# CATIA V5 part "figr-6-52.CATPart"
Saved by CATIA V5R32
Part number: Part1
Bounding box of the stored display mesh (mm): x -46.66 to 43.071, y -43.071 to 47.059, z 0 to 20
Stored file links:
  D:\PROJECTS\Project 2022\CATIA V5 6R 2022\Resources\Part Files\c06_catia_v5_6r2022_prt\figr-6-52.CATPart
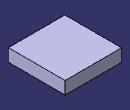
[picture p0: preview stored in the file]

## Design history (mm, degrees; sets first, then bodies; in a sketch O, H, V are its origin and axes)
Body1 (main body)
  Sketch1 on xy-plane, origin (0, 0, 0), H (1, 0, 0), V (0, 1, 0)
    line L1 (-46.6598, 47.0586) -> (43.0706, 47.0586)
    line L2 (43.0706, 47.0586) -> (43.0706, -43.0706)
    line L3 (43.0706, -43.0706) -> (-46.6598, -43.0706)
    line L4 (-46.6598, -43.0706) -> (-46.6598, 47.0586)
    horizontal: L1 H, L3 H
    vertical: L2 V, L4 V
  Pad1: profile Sketch1, direction (0, 0, 1), length 20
